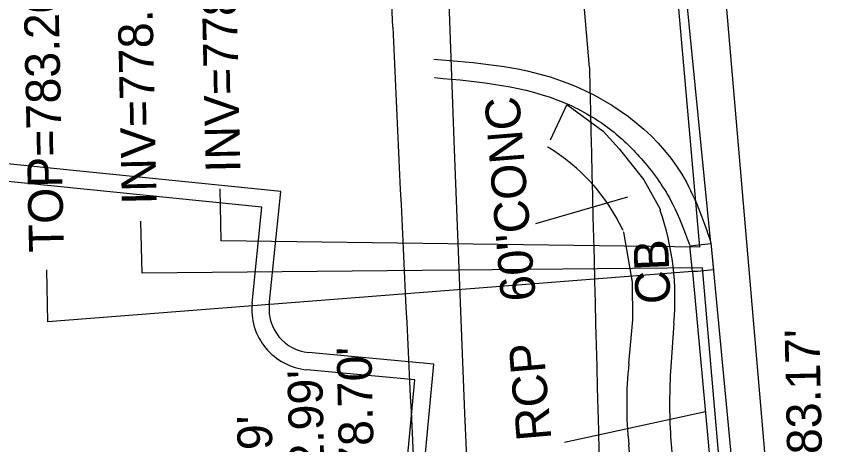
# Model space of a CAD drawing. Extents: x 1627482 to 1629573, y 760826 to 766301.
# Drawn here: x 1628364.1 to 1628457.1, y 761835.1 to 761884.4 of the extents above; entities that cross this region are included whole.
import ezdxf

# ---------------------------------------------------------------- set-up
doc = ezdxf.new("R2010")
doc.units = 0
for name, color, linetype in [('Exist Right of Way Easement Line', 7, 'Continuous'), ('Exist Right of Way Line', 7, 'Continuous'), ('Exist Roads Curbs', 7, 'Continuous'), ('Exist Roads EOP', 7, 'Continuous'), ('Exist Roads EOP Other', 7, 'Continuous'), ('Exist Roads EOP Other Leader', 7, 'Continuous'), ('Exist Roads EOP Other Text', 7, 'Continuous'), ('Exist Roads EOT', 7, 'Continuous'), ('Exist Structure Minor Catch Basin', 7, 'Continuous'), ('Exist Structure Minor Catch Basin Leader', 7, 'Continuous'), ('Exist Structure Minor Catch Basin Text', 7, 'Continuous'), ('Exist Structure Minor Catch Basin Top Elevation', 7, 'Continuous'), ('Exist Structure Minor Pipes RCP 18 Inch', 7, 'Continuous'), ('Exist Structure Minor Pipes RCP 18 Inch Invert', 7, 'Continuous'), ('Exist Structure Minor Pipes RCP 18 Inch Leader', 7, 'Continuous'), ('Exist Structure Minor Pipes RCP 18 Inch Text', 7, 'Continuous'), ('Exist Utilities Gas UG Line SUE', 7, 'Continuous'), ('Exist Utilities Sanitary Sewer Manhole Text', 7, 'Continuous')]:
    doc.layers.add(name, color=color, linetype=linetype)

msp = doc.modelspace()

# ---------------------------------------------------------------- linework, layer by layer
at = {"layer": 'Exist Right of Way Easement Line'}
msp.add_line((1628407.398, 761883.177), (1628398.588, 762076.353), dxfattribs=at)
msp.add_arc((1643489.205, 762580.189), 15097.905, 182.6460645, 183.0590673, dxfattribs=at)
at = {"layer": 'Exist Right of Way Line'}
msp.add_line((1628430.042, 761878.546), (1628416.881, 762036.011), dxfattribs=at)
msp.add_arc((1643455.975, 762228.153), 15030, 181.3328536, 181.6326407, dxfattribs=at)
at = {"layer": 'Exist Roads Curbs'}
for p, q in [((1628412.211, 761877.331), (1628412.228, 761877.368)), ((1628394.506, 761864.264), (1628330.648, 761870.703)), ((1628393.193, 761851.246), (1628394.506, 761864.264)), ((1628441.544, 761858.169), (1628441.574, 761858.148)), ((1628441.922, 761855.032), (1628445.343, 761817.427)), ((1628412.124, 761844.412), (1628397.701, 761845.766)), ((1628405.28, 761771.494), (1628412.124, 761844.412))]:
    msp.add_line(p, q, dxfattribs=at)
msp.add_arc((1628398.168, 761850.744), 5, 174.24244, 264.63743, dxfattribs=at)
msp.add_spline([(1628412.228, 761877.368), (1628427.306, 761874.428), (1628432.632, 761871.273), (1628436.193, 761867.84), (1628439.597, 761862.873), (1628441.544, 761858.169)], degree=3, dxfattribs=at)
at = {"layer": 'Exist Roads EOP'}
for p, q in [((1628412.139, 761879.476), (1628412.132, 761879.487)), ((1628444.034, 761858.382), (1628447.857, 761817.623))]:
    msp.add_line(p, q, dxfattribs=at)
msp.add_lwpolyline([(1628435.5, 761954.954), (1628438.997, 761908.726), (1628443.943, 761858.706)], dxfattribs=at)
msp.add_spline([(1628412.132, 761879.487), (1628426.384, 761877.161), (1628440.678, 761866.26), (1628444.034, 761858.382)], degree=3, dxfattribs=at)
at = {"layer": 'Exist Roads EOP Other'}
for p, q in [((1628427.455, 761874.291), (1628425.534, 761870.179)), ((1628425.217, 761869.389), (1628425.241, 761869.385)), ((1628433.885, 761859.851), (1628433.892, 761859.844)), ((1628433.996, 761859.613), (1628433.982, 761859.603)), ((1628439.754, 761849.146), (1628439.412, 761844.098)), ((1628439.385, 761836.044), (1628443.541, 761785.69)), ((1628438.708, 761785.096), (1628434.583, 761835.139))]:
    msp.add_line(p, q, dxfattribs=at)
for points in [[(1628427.459, 761874.286), (1628431.608, 761871.228), (1628433.463, 761869.195), (1628436.323, 761865.631), (1628438.199, 761862.248), (1628438.202, 761862.094)], [(1628391.204, 761851.446), (1628392.316, 761862.475), (1628330.448, 761868.713)], [(1628434.58, 761844.482), (1628435.026, 761849.53), (1628434.988, 761853.858), (1628433.996, 761859.613)], [(1628391.427, 761774.251), (1628403.468, 761773.595), (1628409.946, 761842.608), (1628397.514, 761843.775)]]:
    msp.add_lwpolyline(points, dxfattribs=at)
msp.add_arc((1628398.168, 761850.744), 7, 174.24244, 264.63743, dxfattribs=at)
for centre, major_axis, ratio, start_param, end_param in [((1628413.848, 761850.387), (-21.751, -4.241), 0.999285, 3.390509, 3.980006), ((1628408.914, 761852.012), (0.138, 30.994), 0.999315, 4.624275, 5.048191), ((1628477.604, 761839.819), (2.372, -43.262), 0.998794, 4.549844, 4.765885), ((1628503.426, 761839.829), (2.714, -64.4), 0.995279, 4.604184, 4.729224)]:
    msp.add_ellipse(centre, major_axis=major_axis, ratio=ratio, start_param=start_param, end_param=end_param, dxfattribs=at)
at = {"layer": 'Exist Roads EOP Other Leader'}
msp.add_line((1628434.433, 761863.636), (1628423.844, 761860.562), dxfattribs=at)
at = {"layer": 'Exist Roads EOT'}
msp.add_line((1628455.375, 761774.372), (1628441.865, 761931.804), dxfattribs=at)
at = {"layer": 'Exist Structure Minor Catch Basin'}
msp.add_lwpolyline([(1628441.918, 761855.089), (1628441.585, 761858.035), (1628442.241, 761858.115), (1628444.011, 761858.307), (1628444.323, 761855.26), (1628442.468, 761855.058), (1628441.976, 761855.075)], dxfattribs=at)
at = {"layer": 'Exist Structure Minor Catch Basin Leader'}
msp.add_lwpolyline([(1628441.918, 761855.089), (1628367.711, 761849.284), (1628367.585, 761855.282)], dxfattribs=at)
at = {"layer": 'Exist Structure Minor Pipes RCP 18 Inch'}
for p, q in [((1628442.743, 761857.886), (1628434.171, 761955.533)), ((1628442.743, 761857.886), (1628434.171, 761955.533)), ((1628446.372, 761817.238), (1628443.062, 761855.497))]:
    msp.add_line(p, q, dxfattribs=at)
at = {"layer": 'Exist Structure Minor Pipes RCP 18 Inch Invert'}
for points in [[(1628442.743, 761857.886), (1628387.649, 761858.581), (1628387.522, 761864.58)], [(1628443.062, 761855.497), (1628378.543, 761854.877), (1628378.417, 761860.875)]]:
    msp.add_lwpolyline(points, dxfattribs=at)
at = {"layer": 'Exist Structure Minor Pipes RCP 18 Inch Leader'}
msp.add_line((1628443.384, 761838.949), (1628427.171, 761835.417), dxfattribs=at)
at = {"layer": 'Exist Utilities Gas UG Line SUE'}
msp.add_lwpolyline([(1628420.258, 761744.11), (1628420.442, 761782.063), (1628417.811, 761791.871), (1628415.699, 761838.775), (1628414.524, 761869.09), (1628413.479, 761897.671), (1628412.767, 761938.427), (1628412.396, 761972.385), (1628412.533, 761994.778), (1628412.282, 762024.831), (1628413.797, 762067.907), (1628415.596, 762097.378)], dxfattribs=at)

# ---------------------------------------------------------------- texts
at = {"layer": 'Exist Roads EOP Other Text'}
msp.add_text('60"CONC', height=4, rotation=94.71216, dxfattribs=at).set_placement((1628423.878, 761851.811))
at = {"layer": 'Exist Structure Minor Catch Basin Text'}
msp.add_text('CB', height=4, rotation=92.25819, dxfattribs=at).set_placement((1628439.377, 761851.398))
at = {"layer": 'Exist Structure Minor Catch Basin Top Elevation'}
for s, p in [("TOP=783.20'", (1628369.542, 761857.324)), ("TOP=782.99'", (1628399.938, 761812.311))]:
    msp.add_text(s, height=4, rotation=91.20525, dxfattribs=at).set_placement(p)
at = {"layer": 'Exist Structure Minor Pipes RCP 18 Inch Invert'}
for s, p in [("INV=778.80'", (1628389.864, 761866.497)), ("INV=778.77'", (1628380.224, 761862.794)), ("INV=778.70'", (1628405.559, 761817.054)), ("INV=778.59'", (1628394.083, 761809.154))]:
    msp.add_text(s, height=4, rotation=91.20525, dxfattribs=at).set_placement(p)
at = {"layer": 'Exist Structure Minor Pipes RCP 18 Inch Text'}
msp.add_text('18" RCP', height=4, rotation=94.90302, dxfattribs=at).set_placement((1628426.475, 761826.474))
at = {"layer": 'Exist Utilities Sanitary Sewer Manhole Text'}
msp.add_text("TOP=783.17'", height=4, rotation=91.20525, dxfattribs=at).set_placement((1628457.168, 761817.011))

doc.saveas('drawing.dxf')
